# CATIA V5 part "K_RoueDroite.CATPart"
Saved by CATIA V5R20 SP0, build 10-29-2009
Part number: roue_droite
Publications: "Corps principal", "largeur de la glissière", "largeur pivot", "Longueur de barres du corps", "Point.1", "Droite.1", "Droite.2", "Droite.3", "Droite.4", "Droite.5"
Bounding box of the stored display mesh (mm): x -100 to 100, y -625 to -575, z -100 to 100
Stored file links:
  G:\Khaled_CFAO_2011\ST2M\ST2M_GR1\cdurantin\cdurantin\Khaled\CAD_ThinkMOTION\K_RoueDroite.CATPart
  G:\Khaled_CFAO_2011\ST2M\ST2M_GR1\cdurantin\cdurantin\Khaled\CAD_ThinkMOTION\K_Part4.CATPart
  G:\Khaled_CFAO_2011\ST2M\ST2M_GR1\cdurantin\cdurantin\Khaled\CAD_ThinkMOTION\K_PivotRoueGauche.CATPart
  G:\Khaled_CFAO_2011\ST2M\ST2M_GR1\cdurantin\cdurantin\Khaled\CAD_ThinkMOTION\K_Corps.CATPart
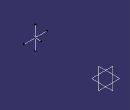
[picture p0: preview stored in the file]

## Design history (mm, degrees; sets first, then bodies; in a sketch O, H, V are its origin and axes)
External parameters (linked from other documents)
  `External.largeur de la glissière` = 100 mm
  `External.largeur pivot` = 125 mm
  `External.Longueur de barres du corps` = 800 mm
Body1 (main body)
  Point1: type OnPlane, Support xy-plane, H 0, V -625 {= -`External.largeur de la glissière` -`External.largeur pivot` -`External.Longueur de barres du corps` /2}, Direction (1, 0, 0)
  Line1: type PtDir, RefPoint Point1, Direction zx-plane, Start 0, End 50
  Line2: type PtDir, RefPoint Point1, Direction yz-plane, Start 0, End 100
  Line3: type PtDir, RefPoint Point1, Direction yz-plane, Start 0, End -100
  Line4: type PtDir, RefPoint Point1, Direction xy-plane, Start 0, End -100
  Line5: type PtDir, RefPoint Point1, Direction xy-plane, Start 0, End 100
